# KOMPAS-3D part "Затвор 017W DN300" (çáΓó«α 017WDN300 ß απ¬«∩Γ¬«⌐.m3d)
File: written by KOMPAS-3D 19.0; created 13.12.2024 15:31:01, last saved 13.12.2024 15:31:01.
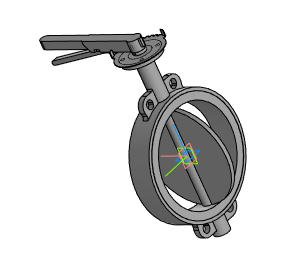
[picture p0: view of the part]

Document properties: Автор: Евгений; Полное имя файла: ..\Затвор 017WDN300.a3d

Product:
- Part/product: Затвор 017W DN300
    Масса: 40.8485

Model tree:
1. Операция без истории:1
